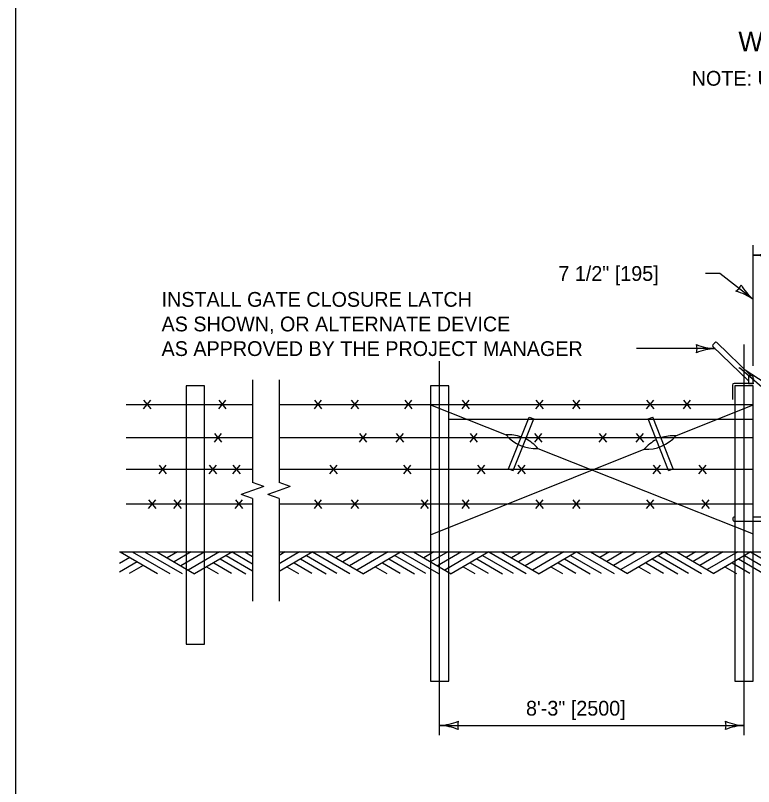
# Model space of a CAD drawing. Extents: x 49991.4 to 50021, y 49987.6 to 50011.4.
# Drawn here: x 50000.336 to 50003.336, y 50005.124 to 50008.258 of the extents above; entities that cross this region are included whole.
import ezdxf

# ---------------------------------------------------------------- set-up
doc = ezdxf.new("R2010")
doc.units = 0
for name, color, linetype in [('Level 1', 7, 'Continuous'), ('Level 2', 7, 'Continuous'), ('Level 3', 7, 'Continuous'), ('Level 4', 7, 'Continuous'), ('Level 5', 7, 'Continuous'), ('Level 6', 7, 'Continuous')]:
    doc.layers.add(name, color=color, linetype=linetype)

msp = doc.modelspace()

# ---------------------------------------------------------------- linework, layer by layer
at = {"layer": 'Level 1'}
for p, q in [((50003.1792, 50006.9279), (50003.1709, 50006.9193)), ((50003.171, 50006.9122), (50003.316, 50006.7727)), ((50003.3258, 50006.793), (50003.1863, 50006.928)), ((50003.4298, 50006.6948), (50003.2786, 50006.8253)), ((50003.4528, 50006.7176), (50003.3022, 50006.8158)), ((50003.3296, 50006.793), (50003.316, 50006.793)), ((50003.316, 50006.793), (50003.316, 50006.7623)), ((50003.3346, 50006.7623), (50003.3346, 50006.788)), ((50003.3374, 50006.7623), (50003.2574, 50006.7623)), ((50003.316, 50006.7623), (50003.3346, 50006.7623)), ((50003.3375, 50006.7817), (50003.3346, 50006.7845)), ((50003.3346, 50006.7716), (50003.3376, 50006.7745)), ((50001.029, 50006.7523), (50001.029, 50006.0773)), ((50001.104, 50006.7523), (50001.029, 50006.7523)), ((50001.104, 50006.0773), (50001.104, 50006.7523)), ((50002.0224, 50006.7523), (50002.0224, 50006.0773)), ((50002.0974, 50006.7523), (50002.0224, 50006.7523)), ((50002.0974, 50006.0773), (50002.0974, 50006.7523)), ((50003.2499, 50006.7548), (50003.2499, 50006.6972)), ((50003.3349, 50006.7523), (50003.2599, 50006.7523)), ((50003.2599, 50006.7523), (50003.2599, 50006.6449)), ((50003.3349, 50006.6547), (50003.3349, 50006.7523)), ((50000.8567, 50006.6592), (50000.8861, 50006.6939)), ((50000.8874, 50006.6592), (50000.8581, 50006.6939)), ((50001.1621, 50006.6592), (50001.1915, 50006.6939)), ((50001.1928, 50006.6592), (50001.1635, 50006.6939)), ((50001.5509, 50006.6592), (50001.5803, 50006.6939)), ((50001.5816, 50006.6592), (50001.5523, 50006.6939)), ((50001.7009, 50006.6592), (50001.7303, 50006.6939)), ((50001.7316, 50006.6592), (50001.7023, 50006.6939)), ((50001.918, 50006.6592), (50001.9474, 50006.6939)), ((50001.9487, 50006.6592), (50001.9194, 50006.6939)), ((50002.1509, 50006.6592), (50002.1803, 50006.6939)), ((50002.1816, 50006.6592), (50002.1523, 50006.6939)), ((50002.4509, 50006.6592), (50002.4803, 50006.6939)), ((50002.4816, 50006.6592), (50002.4523, 50006.6939)), ((50002.6009, 50006.6592), (50002.6303, 50006.6939)), ((50002.6316, 50006.6592), (50002.6023, 50006.6939)), ((50002.9009, 50006.6592), (50002.9303, 50006.6939)), ((50002.9316, 50006.6592), (50002.9023, 50006.6939)), ((50003.0509, 50006.6592), (50003.0803, 50006.6939)), ((50003.0816, 50006.6592), (50003.0523, 50006.6939)), ((50000.7859, 50006.6773), (50001.2994, 50006.6773)), ((50001.4073, 50006.6773), (50003.3349, 50006.6773)), ((50002.0224, 50006.6749), (50002.3305, 50006.5531)), ((50002.0974, 50006.6773), (50003.2599, 50006.6773)), ((50003.0198, 50006.5496), (50003.3349, 50006.6757)), ((50003.2599, 50006.6449), (50003.2599, 50006.0773)), ((50003.3349, 50006.0773), (50003.3349, 50006.6547)), ((50002.0974, 50006.6173), (50003.3349, 50006.6173)), ((50002.3404, 50006.4157), (50002.4236, 50006.6257)), ((50002.359, 50006.4083), (50002.4422, 50006.6183)), ((50002.4236, 50006.6257), (50002.4422, 50006.6183)), ((50002.9075, 50006.6183), (50002.926, 50006.6257)), ((50002.9906, 50006.4083), (50002.9075, 50006.6183)), ((50003.0092, 50006.4157), (50002.926, 50006.6257)), ((50000.7859, 50006.5423), (50001.2994, 50006.5423)), ((50001.1446, 50006.5242), (50001.1739, 50006.5589)), ((50001.1753, 50006.5242), (50001.1459, 50006.5589)), ((50001.4073, 50006.5423), (50003.3349, 50006.5423)), ((50001.7338, 50006.5242), (50001.7631, 50006.5589)), ((50001.7645, 50006.5242), (50001.7351, 50006.5589)), ((50001.8838, 50006.5242), (50001.9131, 50006.5589)), ((50001.9145, 50006.5242), (50001.8851, 50006.5589)), ((50002.1838, 50006.5242), (50002.2131, 50006.5589)), ((50002.2145, 50006.5242), (50002.1851, 50006.5589)), ((50002.4463, 50006.5242), (50002.4756, 50006.5589)), ((50002.477, 50006.5242), (50002.4476, 50006.5589)), ((50002.7088, 50006.5242), (50002.7381, 50006.5589)), ((50002.7395, 50006.5242), (50002.7101, 50006.5589)), ((50002.8588, 50006.5242), (50002.8881, 50006.5589)), ((50002.8895, 50006.5242), (50002.8601, 50006.5589)), ((50002.0224, 50006.1469), (50002.8914, 50006.4945)), ((50002.459, 50006.498), (50003.3349, 50006.1511)), ((50000.7859, 50006.4133), (50001.2994, 50006.4133)), ((50000.9196, 50006.3952), (50000.9489, 50006.4299)), ((50000.9503, 50006.3952), (50000.9209, 50006.4299)), ((50001.1236, 50006.3952), (50001.1529, 50006.4299)), ((50001.1543, 50006.3952), (50001.1249, 50006.4299)), ((50001.2196, 50006.3952), (50001.2489, 50006.4299)), ((50001.2503, 50006.3952), (50001.2209, 50006.4299)), ((50001.4073, 50006.4133), (50003.3349, 50006.4133)), ((50001.6138, 50006.3952), (50001.6431, 50006.4299)), ((50001.6445, 50006.3952), (50001.6151, 50006.4299)), ((50001.9138, 50006.3952), (50001.9431, 50006.4299)), ((50001.9445, 50006.3952), (50001.9151, 50006.4299)), ((50002.2138, 50006.3952), (50002.2431, 50006.4299)), ((50002.2445, 50006.3952), (50002.2151, 50006.4299)), ((50002.3404, 50006.4157), (50002.359, 50006.4083)), ((50002.378, 50006.3952), (50002.4073, 50006.4299)), ((50002.4087, 50006.3952), (50002.3793, 50006.4299)), ((50002.9282, 50006.3952), (50002.9575, 50006.4299)), ((50002.9589, 50006.3952), (50002.9295, 50006.4299)), ((50002.9906, 50006.4083), (50003.0092, 50006.4157)), ((50003.1138, 50006.3952), (50003.1431, 50006.4299)), ((50003.1445, 50006.3952), (50003.1151, 50006.4299)), ((50000.8767, 50006.2542), (50000.9061, 50006.2889)), ((50000.9074, 50006.2542), (50000.8781, 50006.2889)), ((50000.9795, 50006.2542), (50001.0089, 50006.2889)), ((50001.0102, 50006.2542), (50000.9809, 50006.2889)), ((50001.2295, 50006.2542), (50001.2589, 50006.2889)), ((50001.2602, 50006.2542), (50001.2309, 50006.2889)), ((50001.5509, 50006.2542), (50001.5803, 50006.2889)), ((50001.5816, 50006.2542), (50001.5523, 50006.2889)), ((50001.7009, 50006.2542), (50001.7303, 50006.2889)), ((50001.7316, 50006.2542), (50001.7023, 50006.2889)), ((50001.9842, 50006.2542), (50002.0136, 50006.2889)), ((50002.0149, 50006.2542), (50001.9856, 50006.2889)), ((50002.1509, 50006.2542), (50002.1803, 50006.2889)), ((50002.1816, 50006.2542), (50002.1523, 50006.2889)), ((50002.4509, 50006.2542), (50002.4803, 50006.2889)), ((50002.4816, 50006.2542), (50002.4523, 50006.2889)), ((50002.6009, 50006.2542), (50002.6303, 50006.2889)), ((50002.6316, 50006.2542), (50002.6023, 50006.2889)), ((50002.9009, 50006.2542), (50002.9303, 50006.2889)), ((50002.9316, 50006.2542), (50002.9023, 50006.2889)), ((50003.1259, 50006.2542), (50003.1553, 50006.2889)), ((50003.1566, 50006.2542), (50003.1273, 50006.2889)), ((50000.7859, 50006.2723), (50001.2994, 50006.2723)), ((50001.4073, 50006.2723), (50003.3349, 50006.2723)), ((50003.2599, 50006.2023), (50003.461, 50006.2023)), ((50003.3349, 50006.2199), (50003.4298, 50006.2199)), ((50000.7586, 50006.0773), (50001.2994, 50006.0773)), ((50000.7607, 50006.0773), (50000.9129, 50005.9894)), ((50000.8107, 50006.0773), (50000.9629, 50005.9894)), ((50000.8607, 50006.0773), (50001.0129, 50005.9894)), ((50000.9107, 50006.0773), (50001.0641, 50005.9887)), ((50000.9941, 50006.0773), (50000.9524, 50006.0532)), ((50001.0502, 50006.0773), (50000.9804, 50006.0371)), ((50001.1054, 50006.0773), (50001.008, 50006.0211)), ((50001.1645, 50006.0773), (50001.0376, 50006.004)), ((50001.2175, 50006.0773), (50001.0641, 50005.9887)), ((50001.2167, 50006.0773), (50001.2994, 50006.0295)), ((50001.2677, 50006.0773), (50001.2994, 50006.059)), ((50001.4073, 50006.0773), (50003.3634, 50006.0773)), ((50001.432, 50006.0773), (50001.4073, 50006.0631)), ((50001.544, 50006.0773), (50001.4073, 50005.9984)), ((50001.491, 50006.0773), (50001.4073, 50006.0289)), ((50001.5432, 50006.0773), (50001.6954, 50005.9894)), ((50001.5966, 50006.0773), (50001.75, 50005.9887)), ((50001.68, 50006.0773), (50001.6383, 50006.0532)), ((50001.7361, 50006.0773), (50001.6663, 50006.0371)), ((50001.7913, 50006.0773), (50001.6939, 50006.0211)), ((50001.8504, 50006.0773), (50001.7235, 50006.004)), ((50001.9034, 50006.0773), (50001.75, 50005.9887)), ((50001.9026, 50006.0773), (50002.0548, 50005.9894)), ((50001.9536, 50006.0773), (50002.107, 50005.9887)), ((50002.037, 50006.0773), (50001.9953, 50006.0532)), ((50002.0931, 50006.0773), (50002.0233, 50006.0371)), ((50002.1483, 50006.0773), (50002.0509, 50006.0211)), ((50002.2074, 50006.0773), (50002.0805, 50006.004)), ((50002.2604, 50006.0773), (50002.107, 50005.9887)), ((50002.2596, 50006.0773), (50002.4118, 50005.9894)), ((50002.3106, 50006.0773), (50002.464, 50005.9887)), ((50002.394, 50006.0773), (50002.3523, 50006.0532)), ((50002.4501, 50006.0773), (50002.3803, 50006.0371)), ((50002.5053, 50006.0773), (50002.4079, 50006.0211)), ((50002.5644, 50006.0773), (50002.4375, 50006.004)), ((50002.6174, 50006.0773), (50002.464, 50005.9887)), ((50002.6166, 50006.0773), (50002.7688, 50005.9894)), ((50002.6727, 50006.0773), (50002.8232, 50005.9904)), ((50002.7502, 50006.0773), (50002.7115, 50006.0549)), ((50002.8063, 50006.0773), (50002.7394, 50006.0388)), ((50002.8615, 50006.0773), (50002.7671, 50006.0228)), ((50002.9206, 50006.0773), (50002.7967, 50006.0057)), ((50002.9736, 50006.0773), (50002.8232, 50005.9904)), ((50002.9728, 50006.0773), (50003.125, 50005.9894)), ((50003.0238, 50006.0773), (50003.1743, 50005.9904)), ((50003.1013, 50006.0773), (50003.0626, 50006.0549)), ((50003.1574, 50006.0773), (50003.0905, 50006.0388)), ((50003.2126, 50006.0773), (50003.1182, 50006.0228)), ((50003.2717, 50006.0773), (50003.1478, 50006.0057)), ((50003.3247, 50006.0773), (50003.1743, 50005.9904)), ((50003.3239, 50006.0773), (50003.4155, 50006.0243)), ((50003.3349, 50006.0773), (50007.5434, 50006.0773)), ((50000.8, 50006.0546), (50000.7586, 50006.0307)), ((50000.8308, 50006.0368), (50000.7586, 50005.9952)), ((50001.1681, 50006.0488), (50001.2721, 50005.9887)), ((50001.1918, 50006.0624), (50001.2994, 50006.0002)), ((50001.4946, 50006.0488), (50001.5986, 50005.9887)), ((50001.5182, 50006.0624), (50001.6426, 50005.9906)), ((50001.854, 50006.0488), (50001.958, 50005.9887)), ((50001.8777, 50006.0624), (50002.002, 50005.9906)), ((50002.211, 50006.0488), (50002.315, 50005.9887)), ((50002.2347, 50006.0624), (50002.359, 50005.9906)), ((50002.568, 50006.0488), (50002.672, 50005.9887)), ((50002.5917, 50006.0624), (50002.716, 50005.9906)), ((50002.9242, 50006.0488), (50003.0282, 50005.9887)), ((50002.9479, 50006.0624), (50003.0722, 50005.9906)), ((50003.2753, 50006.0488), (50003.3793, 50005.9887)), ((50003.299, 50006.0624), (50003.4286, 50005.9875)), ((50000.8554, 50006.0226), (50000.7978, 50005.9894)), ((50001.1125, 50006.0167), (50001.1596, 50005.9894)), ((50001.1418, 50006.0336), (50001.214, 50005.9918)), ((50001.439, 50006.0167), (50001.4861, 50005.9894)), ((50001.4682, 50006.0336), (50001.5405, 50005.9918)), ((50001.7984, 50006.0167), (50001.8455, 50005.9894)), ((50001.8277, 50006.0336), (50001.8999, 50005.9918)), ((50002.1554, 50006.0167), (50002.2025, 50005.9894)), ((50002.1847, 50006.0336), (50002.2569, 50005.9918)), ((50002.5124, 50006.0167), (50002.5595, 50005.9894)), ((50002.5417, 50006.0336), (50002.6139, 50005.9918)), ((50002.8686, 50006.0167), (50002.9157, 50005.9894)), ((50002.8979, 50006.0336), (50002.9701, 50005.9918)), ((50003.2197, 50006.0167), (50003.2668, 50005.9894)), ((50003.249, 50006.0336), (50003.3212, 50005.9918))]:
    msp.add_line(p, q, dxfattribs=at)
msp.add_lwpolyline([(50008.6146, 50011.2628), (50000.3356, 50011.2628), (50000.3356, 50000.0624), (50008.6146, 50000.0624)], close=True, dxfattribs=at)
msp.add_circle((50003.2786, 50006.8253), 0.000949, dxfattribs=at)
for centre, radius, start, end in [((50003.1745, 50006.9158), 0.005, 135.6683, 226.1745), ((50003.1828, 50006.9244), 0.005, 45.9359, 135.927), ((50003.3296, 50006.788), 0.005, 0, 90), ((50003.2574, 50006.7548), 0.0075, 90, 180), ((50002.3402, 50006.3984), 0.155, 70.692, 93.5951), ((50002.4493, 50006.6528), 0.155, 220.0078, 273.5951), ((50002.3402, 50006.3984), 0.155, 40.0078, 63.2871), ((50002.901, 50006.6492), 0.155, 266.4347, 320.0376), ((50003.0102, 50006.3949), 0.155, 86.4348, 109.12), ((50003.0102, 50006.3949), 0.155, 116.5245, 140.0376), ((50003.2599, 50006.2111), 0.0088, 90, 270)]:
    msp.add_arc(centre, radius, start, end, dxfattribs=at)
at = {"layer": 'Level 3'}
for p, q in [((50003.335, 50006.8344), (50003.3349, 50007.3236)), ((50003.3349, 50007.2836), (50005.7348, 50007.2836)), ((50003.1986, 50007.2089), (50003.1411, 50007.2091)), ((50003.3349, 50007.1036), (50003.1986, 50007.2089)), ((50003.1797, 50006.9038), (50002.8597, 50006.9038)), ((50002.0599, 50005.3723), (50003.2974, 50005.3723))]:
    msp.add_line(p, q, dxfattribs=at)
for centre, radius, start, end in [((50003.3234, 50007.5163), 0.233, 272.8273, 292.0772), ((50003.3257, 50007.0615), 0.2223, 67.456, 87.6395), ((50003.2335, 50007.1819), 0.0548, 304.4532, 340.1756), ((50003.478, 50007.2738), 0.2223, 209.7704, 229.9539), ((50003.2018, 50006.9124), 0.233, 55.1417, 74.3915), ((50003.1889, 50007.1259), 0.2223, 247.456, 267.6395), ((50003.0515, 50006.9038), 0.0548, 342.1388, 17.8612), ((50003.1912, 50006.6711), 0.233, 92.8273, 112.0772), ((50002.0484, 50005.605), 0.233, 272.8273, 292.0772), ((50002.1881, 50005.3723), 0.0548, 162.1388, 197.8612), ((50003.3066, 50005.5944), 0.2223, 247.456, 267.6395), ((50003.1692, 50005.3723), 0.0548, 342.1388, 17.8612), ((50002.0507, 50005.1502), 0.2223, 67.456, 87.6395), ((50003.3089, 50005.1396), 0.233, 92.8273, 112.0772)]:
    msp.add_arc(centre, radius, start, end, dxfattribs=at)
at = {"layer": 'Level 4'}
for p, q in [((50001.029, 50006.0773), (50001.029, 50005.7023)), ((50001.104, 50005.7023), (50001.104, 50006.0773)), ((50002.0224, 50006.0773), (50002.0224, 50005.5523)), ((50002.0974, 50005.5523), (50002.0974, 50006.0773)), ((50003.2599, 50006.0773), (50003.2599, 50005.5523)), ((50003.3349, 50005.5523), (50003.3349, 50006.0773)), ((50001.029, 50005.7023), (50001.104, 50005.7023)), ((50002.0224, 50005.5523), (50002.0974, 50005.5523)), ((50003.2599, 50005.5523), (50003.3349, 50005.5523))]:
    msp.add_line(p, q, dxfattribs=at)
at = {"layer": 'Level 5'}
for p, q in [((50003.2974, 50005.3323), (50003.2974, 50006.9205)), ((50002.0599, 50005.3323), (50002.0599, 50006.8523))]:
    msp.add_line(p, q, dxfattribs=at)
at = {"layer": 'Level 6'}
for p, q in [((50001.2994, 50006.7773), (50001.2994, 50006.3597)), ((50001.4073, 50006.7773), (50001.4073, 50006.3597)), ((50001.3451, 50006.3435), (50001.2994, 50006.3597)), ((50001.453, 50006.3435), (50001.4073, 50006.3597)), ((50001.2994, 50006.3273), (50001.2537, 50006.3111)), ((50001.3451, 50006.3435), (50001.2994, 50006.3273)), ((50001.4073, 50006.3273), (50001.3616, 50006.3111)), ((50001.453, 50006.3435), (50001.4073, 50006.3273)), ((50001.2994, 50006.2949), (50001.2537, 50006.3111)), ((50001.2994, 50006.2949), (50001.2994, 50005.8773)), ((50001.4073, 50006.2949), (50001.3616, 50006.3111)), ((50001.4073, 50006.2949), (50001.4073, 50005.8773))]:
    msp.add_line(p, q, dxfattribs=at)

# ---------------------------------------------------------------- texts
at = {"layer": 'Level 2'}
for s, height, p in [('WOOD FARM ENTRANCE GATE (TYPE G-1)', 0.08, (50003.2742, 50008.1123)), ('NOTE: USE 10d NAILS AND CLINCH FOR GATE CONSTRUCTION.', 0.06, (50003.0845, 50007.9723)), ('7 1/2" [195]', 0.06, (50002.5426, 50007.1791)), ('INSTALL GATE CLOSURE LATCH', 0.06, (50000.9296, 50007.0738)), ('AS SHOWN, OR ALTERNATE DEVICE', 0.06, (50000.9296, 50006.9738)), ('AS APPROVED BY THE PROJECT MANAGER', 0.06, (50000.9296, 50006.8738)), ('8\'-3" [2500]', 0.06, (50002.4111, 50005.4123))]:
    msp.add_text(s, height=height, dxfattribs=at).set_placement(p)

doc.saveas('drawing.dxf')
